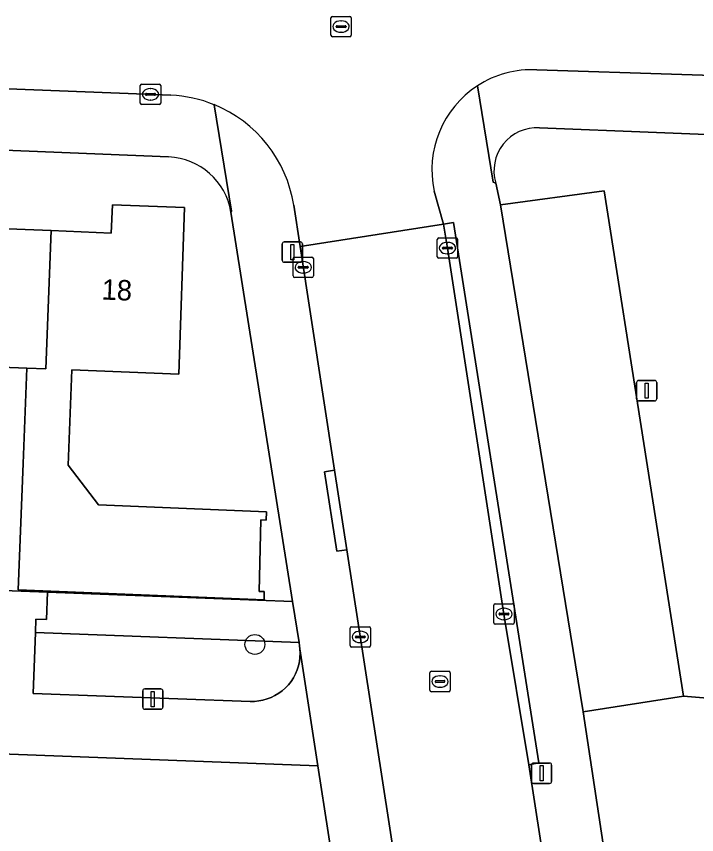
# Model space of a CAD drawing. Extents: x 160077 to 160948, y 386481 to 387498.
# Drawn here: x 160779.11 to 160812.49, y 386759.71 to 386799.88 of the extents above; entities that cross this region are included whole.
import ezdxf

# ---------------------------------------------------------------- set-up
doc = ezdxf.new("R2010")
doc.units = 0
for name, color, linetype in [('IMGEO_Boom', 7, 'Continuous'), ('IMGEO_Erf', 7, 'Continuous'), ('IMGEO_Groenvoorziening', 7, 'Continuous'), ('IMGEO_Kolk', 7, 'Continuous'), ('IMGEO_Lichtmast', 7, 'Continuous'), ('IMGEO_Pand', 7, 'Continuous'), ('IMGEO_Pand_nummerreeks', 7, 'Continuous'), ('IMGEO_Parkeervlak_open', 7, 'Continuous'), ('IMGEO_Rijbaan_lokaal_open', 7, 'Continuous'), ('IMGEO_Rioolput', 7, 'Continuous'), ('IMGEO_Voetpad_open', 7, 'Continuous')]:
    doc.layers.add(name, color=color, linetype=linetype)

msp = doc.modelspace()

# ---------------------------------------------------------------- linework, layer by layer
at = {"layer": 'IMGEO_Boom'}
msp.add_circle((160790.816, 386769.045), 0.489, dxfattribs=at)
at = {"layer": 'IMGEO_Erf'}
for points in [[(160786.582, 386792.975), (160742.734, 386794.767)], [(160728.911, 386794.383), (160726.113, 386793.887), (160729.208, 386773.55), (160739.777, 386773.151), (160742.325, 386773.055), (160752.485, 386772.671), (160755.107, 386772.572), (160765.268, 386772.187), (160767.757, 386772.092), (160778.031, 386771.702), (160780.646, 386771.604), (160792.664, 386771.147), (160789.642, 386790.266)], [(160774.463, 386789.613), (160780.828, 386789.358), (160783.769, 386789.24), (160783.823, 386790.625), (160787.36, 386790.487), (160787.081, 386782.314), (160781.843, 386782.518), (160781.659, 386777.84), (160783.144, 386775.898), (160791.386, 386775.56), (160791.376, 386775.148), (160791.104, 386775.155), (160791.018, 386771.649), (160791.271, 386771.643), (160791.265, 386771.227), (160779.206, 386771.72), (160779.444, 386777.926), (160779.627, 386782.604), (160775.467, 386782.766)]]:
    msp.add_lwpolyline(points, dxfattribs=at)
msp.add_lwpolyline([(160795.925, 386750), (160793.898, 386763.085), (160730.396, 386765.489), (160732.727, 386750), (160733.656, 386743.829), (160744.313, 386743.428), (160746.852, 386743.334), (160757.001, 386742.953), (160759.549, 386742.857), (160769.844, 386742.471), (160772.371, 386742.376), (160782.604, 386741.967), (160785.258, 386741.861), (160797.26, 386741.38)], close=True, dxfattribs=at)
msp.add_arc((160786.46, 386789.755), 3.222, 9.1259, 87.8375, dxfattribs=at)
at = {"layer": 'IMGEO_Groenvoorziening'}
for points in [[(160816.262, 386793.948), (160804.774, 386794.408)], [(160802.632, 386791.694), (160802.867, 386790.622), (160807.956, 386791.312), (160811.851, 386766.514), (160815.188, 386766.228), (160816.262, 386793.948)]]:
    msp.add_lwpolyline(points, dxfattribs=at)
for points in [[(160792.982, 386769.133), (160792.664, 386771.147), (160780.646, 386771.604), (160780.595, 386770.268), (160780.076, 386770.288), (160780.051, 386769.625)], [(160790.579, 386766.248), (160790.791, 386766.25), (160791.002, 386766.271), (160791.21, 386766.31), (160791.414, 386766.368), (160791.612, 386766.444), (160791.802, 386766.537), (160791.983, 386766.647), (160792.154, 386766.773), (160792.312, 386766.913), (160792.458, 386767.067), (160792.589, 386767.233), (160792.705, 386767.411), (160792.804, 386767.598), (160792.887, 386767.793), (160792.952, 386767.995), (160792.998, 386768.202), (160793.026, 386768.412), (160793.034, 386768.623), (160793.024, 386768.835), (160793.006, 386768.982), (160792.982, 386769.133), (160780.051, 386769.625), (160779.937, 386766.637)], [(160823.518, 386765.871), (160820.354, 386766.006), (160815.188, 386766.228), (160811.851, 386766.514), (160806.916, 386765.741), (160808.027, 386758.373), (160823.217, 386757.574)]]:
    msp.add_lwpolyline(points, close=True, dxfattribs=at)
msp.add_arc((160804.661, 386792.295), 2.116, 86.9395, 196.4966, dxfattribs=at)
at = {"layer": 'IMGEO_Kolk'}
for p, q in [((160785.195, 386795.623), (160785.195, 386796.475)), ((160785.27, 386796.549), (160786.122, 386796.549)), ((160785.683, 386796.329), (160785.708, 386796.329)), ((160786.196, 386796.475), (160786.196, 386795.623)), ((160785.454, 386796.043), (160785.454, 386796.055)), ((160785.892, 386796.006), (160785.494, 386796.006)), ((160785.497, 386796.092), (160785.895, 386796.092)), ((160785.938, 386796.055), (160785.938, 386796.043)), ((160786.122, 386795.549), (160785.27, 386795.549)), ((160785.706, 386795.769), (160785.681, 386795.769)), ((160799.764, 386788.075), (160799.764, 386788.927)), ((160799.839, 386789.001), (160800.691, 386789.001)), ((160800.252, 386788.781), (160800.277, 386788.781)), ((160800.765, 386788.927), (160800.765, 386788.075)), ((160800.023, 386788.495), (160800.023, 386788.507)), ((160800.461, 386788.458), (160800.063, 386788.458)), ((160800.066, 386788.544), (160800.464, 386788.544)), ((160800.507, 386788.507), (160800.507, 386788.495)), ((160792.688, 386787.132), (160792.688, 386787.984)), ((160792.763, 386788.058), (160793.615, 386788.058)), ((160793.689, 386787.984), (160793.689, 386787.132)), ((160800.691, 386788.001), (160799.839, 386788.001)), ((160800.275, 386788.221), (160800.25, 386788.221)), ((160792.947, 386787.552), (160792.947, 386787.564)), ((160793.385, 386787.515), (160792.987, 386787.515)), ((160792.99, 386787.601), (160793.388, 386787.601)), ((160793.176, 386787.838), (160793.201, 386787.838)), ((160793.431, 386787.564), (160793.431, 386787.552)), ((160793.199, 386787.278), (160793.174, 386787.278)), ((160793.615, 386787.058), (160792.763, 386787.058)), ((160802.611, 386771.039), (160803.463, 386771.039)), ((160802.536, 386770.113), (160802.536, 386770.965)), ((160803.024, 386770.819), (160803.049, 386770.819)), ((160803.537, 386770.965), (160803.537, 386770.113)), ((160802.795, 386770.533), (160802.795, 386770.545)), ((160803.233, 386770.496), (160802.835, 386770.496)), ((160802.838, 386770.582), (160803.236, 386770.582)), ((160803.047, 386770.259), (160803.022, 386770.259)), ((160803.279, 386770.545), (160803.279, 386770.533)), ((160795.489, 386768.988), (160795.489, 386769.84)), ((160795.564, 386769.914), (160796.416, 386769.914)), ((160796.49, 386769.84), (160796.49, 386768.988)), ((160803.463, 386770.039), (160802.611, 386770.039)), ((160795.748, 386769.408), (160795.748, 386769.42)), ((160795.791, 386769.457), (160796.189, 386769.457)), ((160795.977, 386769.694), (160796.002, 386769.694)), ((160796.232, 386769.42), (160796.232, 386769.408)), ((160796.186, 386769.371), (160795.788, 386769.371)), ((160796, 386769.134), (160795.975, 386769.134)), ((160796.416, 386768.914), (160795.564, 386768.914))]:
    msp.add_line(p, q, dxfattribs=at)
for points in [[(160785.195, 386795.623), (160785.195, 386796.475)], [(160785.27, 386796.549), (160786.122, 386796.549)], [(160786.196, 386796.475), (160786.196, 386795.623)], [(160786.122, 386795.549), (160785.27, 386795.549)], [(160799.764, 386788.075), (160799.764, 386788.927)], [(160799.839, 386789.001), (160800.691, 386789.001)], [(160800.765, 386788.927), (160800.765, 386788.075)], [(160792.688, 386787.132), (160792.688, 386787.984)], [(160792.763, 386788.058), (160793.615, 386788.058)], [(160793.689, 386787.984), (160793.689, 386787.132)], [(160800.691, 386788.001), (160799.839, 386788.001)], [(160793.615, 386787.058), (160792.763, 386787.058)], [(160802.611, 386771.039), (160803.463, 386771.039)], [(160802.536, 386770.113), (160802.536, 386770.965)], [(160803.537, 386770.965), (160803.537, 386770.113)], [(160795.489, 386768.988), (160795.489, 386769.84)], [(160795.564, 386769.914), (160796.416, 386769.914)], [(160796.49, 386769.84), (160796.49, 386768.988)], [(160803.463, 386770.039), (160802.611, 386770.039)], [(160796.416, 386768.914), (160795.564, 386768.914)]]:
    msp.add_lwpolyline(points, dxfattribs=at)
for centre, radius, start, end in [((160785.272, 386796.473), 0.0765, 91.552, 178.448), ((160785.272, 386796.473), 0.0765, 91.552, 178.448), ((160786.12, 386796.473), 0.0765, 1.552, 88.448), ((160786.12, 386796.473), 0.0765, 1.552, 88.448), ((160785.494, 386796.052), 0.0403, 85.8775, 175.7526), ((160785.491, 386796.042), 0.0366, 178.938, 274.7102), ((160785.895, 386796.049), 0.043, 264.8664, 352.4533), ((160785.899, 386796.054), 0.0386, 1.7309, 96.639), ((160785.272, 386795.625), 0.0765, 181.552, 268.448), ((160785.272, 386795.625), 0.0765, 181.552, 268.448), ((160786.12, 386795.625), 0.0765, 271.552, 358.448), ((160786.12, 386795.625), 0.0765, 271.552, 358.448), ((160799.841, 386788.925), 0.0765, 91.552, 178.448), ((160799.841, 386788.925), 0.0765, 91.552, 178.448), ((160800.689, 386788.925), 0.0765, 1.552, 88.448), ((160800.689, 386788.925), 0.0765, 1.552, 88.448), ((160800.063, 386788.504), 0.0403, 85.8775, 175.7526), ((160800.06, 386788.494), 0.0366, 178.938, 274.7102), ((160800.464, 386788.501), 0.043, 264.8664, 352.4533), ((160800.468, 386788.506), 0.0386, 1.7309, 96.639), ((160792.765, 386787.982), 0.0765, 91.552, 178.448), ((160792.765, 386787.982), 0.0765, 91.552, 178.448), ((160793.613, 386787.982), 0.0765, 1.552, 88.448), ((160793.613, 386787.982), 0.0765, 1.552, 88.448), ((160799.841, 386788.077), 0.0765, 181.552, 268.448), ((160799.841, 386788.077), 0.0765, 181.552, 268.448), ((160800.689, 386788.077), 0.0765, 271.552, 358.448), ((160800.689, 386788.077), 0.0765, 271.552, 358.448), ((160792.987, 386787.561), 0.0403, 85.8775, 175.7526), ((160792.984, 386787.551), 0.0366, 178.938, 274.7102), ((160793.388, 386787.558), 0.043, 264.8664, 352.4533), ((160793.392, 386787.563), 0.0386, 1.7309, 96.639), ((160792.765, 386787.134), 0.0765, 181.552, 268.448), ((160792.765, 386787.134), 0.0765, 181.552, 268.448), ((160793.613, 386787.134), 0.0765, 271.552, 358.448), ((160793.613, 386787.134), 0.0765, 271.552, 358.448), ((160802.613, 386770.963), 0.0765, 91.552, 178.448), ((160802.613, 386770.963), 0.0765, 91.552, 178.448), ((160803.461, 386770.963), 0.0765, 1.552, 88.448), ((160803.461, 386770.963), 0.0765, 1.552, 88.448), ((160802.835, 386770.542), 0.0403, 85.8775, 175.7526), ((160802.832, 386770.532), 0.0366, 178.938, 274.7102), ((160803.236, 386770.539), 0.043, 264.8664, 352.4533), ((160803.24, 386770.544), 0.0386, 1.7309, 96.639), ((160795.566, 386769.838), 0.0765, 91.552, 178.448), ((160795.566, 386769.838), 0.0765, 91.552, 178.448), ((160796.414, 386769.838), 0.0765, 1.552, 88.448), ((160796.414, 386769.838), 0.0765, 1.552, 88.448), ((160802.613, 386770.115), 0.0765, 181.552, 268.448), ((160802.613, 386770.115), 0.0765, 181.552, 268.448), ((160803.461, 386770.115), 0.0765, 271.552, 358.448), ((160803.461, 386770.115), 0.0765, 271.552, 358.448), ((160795.788, 386769.417), 0.0403, 85.8775, 175.7526), ((160795.785, 386769.407), 0.0366, 178.938, 274.7102), ((160796.189, 386769.414), 0.043, 264.8664, 352.4533), ((160796.193, 386769.419), 0.0386, 1.7309, 96.639), ((160795.566, 386768.99), 0.0765, 181.552, 268.448), ((160795.566, 386768.99), 0.0765, 181.552, 268.448), ((160796.414, 386768.99), 0.0765, 271.552, 358.448), ((160796.414, 386768.99), 0.0765, 271.552, 358.448)]:
    msp.add_arc(centre, radius, start, end, dxfattribs=at)
for centre, major_axis, ratio, start_param, end_param in [((160785.682, 386796.049), (-0.387, 0.002), 0.722429, 4.712389, 7.853982), ((160785.707, 386796.049), (-0.39, 0.002), 0.717154, 1.570796, 4.712389), ((160800.251, 386788.501), (-0.387, 0.002), 0.722429, 4.712389, 7.853982), ((160800.276, 386788.501), (-0.39, 0.002), 0.717154, 1.570796, 4.712389), ((160793.175, 386787.558), (-0.387, 0.002), 0.722429, 4.712389, 7.853982), ((160793.2, 386787.558), (-0.39, 0.002), 0.717154, 1.570796, 4.712389), ((160803.023, 386770.539), (-0.387, 0.002), 0.722429, 4.712389, 7.853982), ((160803.048, 386770.539), (-0.39, 0.002), 0.717154, 1.570796, 4.712389), ((160795.976, 386769.414), (-0.387, 0.002), 0.722429, 4.712389, 7.853982), ((160796.001, 386769.414), (-0.39, 0.002), 0.717154, 1.570796, 4.712389)]:
    msp.add_ellipse(centre, major_axis=major_axis, ratio=ratio, start_param=start_param, end_param=end_param, dxfattribs=at)
at = {"layer": 'IMGEO_Lichtmast'}
for p, q in [((160792.159, 386787.904), (160792.159, 386788.704)), ((160792.159, 386788.704), (160792.159, 386787.904)), ((160792.259, 386788.804), (160793.049, 386788.804)), ((160793.049, 386788.804), (160792.259, 386788.804)), ((160793.149, 386788.704), (160793.149, 386787.904)), ((160793.149, 386787.904), (160793.149, 386788.704)), ((160793.049, 386787.804), (160792.259, 386787.804)), ((160792.259, 386787.804), (160793.049, 386787.804)), ((160809.54, 386781.103), (160809.54, 386781.903)), ((160809.54, 386781.903), (160809.54, 386781.103)), ((160809.64, 386782.003), (160810.43, 386782.003)), ((160810.43, 386782.003), (160809.64, 386782.003)), ((160810.53, 386781.903), (160810.53, 386781.103)), ((160810.53, 386781.103), (160810.53, 386781.903)), ((160810.43, 386781.003), (160809.64, 386781.003)), ((160809.64, 386781.003), (160810.43, 386781.003)), ((160785.312, 386765.964), (160785.312, 386766.764)), ((160785.312, 386766.764), (160785.312, 386765.964)), ((160785.412, 386766.864), (160786.202, 386766.864)), ((160786.202, 386766.864), (160785.412, 386766.864)), ((160786.302, 386766.764), (160786.302, 386765.964)), ((160786.302, 386765.964), (160786.302, 386766.764)), ((160786.202, 386765.864), (160785.412, 386765.864)), ((160785.412, 386765.864), (160786.202, 386765.864)), ((160804.386, 386762.324), (160804.386, 386763.124)), ((160804.386, 386763.124), (160804.386, 386762.324)), ((160804.486, 386763.224), (160805.276, 386763.224)), ((160805.276, 386763.224), (160804.486, 386763.224)), ((160805.376, 386763.124), (160805.376, 386762.324)), ((160805.376, 386762.324), (160805.376, 386763.124)), ((160805.276, 386762.224), (160804.486, 386762.224)), ((160804.486, 386762.224), (160805.276, 386762.224))]:
    msp.add_line(p, q, dxfattribs=at)
for points in [[(160792.579, 386788.679), (160792.729, 386788.679), (160792.729, 386787.929), (160792.579, 386787.929), (160792.579, 386788.679)], [(160809.96, 386781.878), (160810.11, 386781.878), (160810.11, 386781.128), (160809.96, 386781.128), (160809.96, 386781.878)], [(160785.732, 386766.739), (160785.882, 386766.739), (160785.882, 386765.989), (160785.732, 386765.989), (160785.732, 386766.739)], [(160804.806, 386763.099), (160804.956, 386763.099), (160804.956, 386762.349), (160804.806, 386762.349), (160804.806, 386763.099)]]:
    msp.add_lwpolyline(points, dxfattribs=at)
for centre, start, end in [((160792.259, 386788.704), 90, 180), ((160792.259, 386788.704), 90, 180), ((160793.049, 386788.704), 0, 90), ((160793.049, 386788.704), 360, 90), ((160792.259, 386787.904), 180, 270), ((160792.259, 386787.904), 180, 270), ((160793.049, 386787.904), 270, 0), ((160793.049, 386787.904), 270, 0), ((160809.64, 386781.903), 90, 180), ((160809.64, 386781.903), 90, 180), ((160810.43, 386781.903), 0, 90), ((160810.43, 386781.903), 360, 90), ((160809.64, 386781.103), 180, 270), ((160809.64, 386781.103), 180, 270), ((160810.43, 386781.103), 270, 0), ((160810.43, 386781.103), 270, 0), ((160785.412, 386766.764), 90, 180), ((160785.412, 386766.764), 90, 180), ((160786.202, 386766.764), 0, 90), ((160786.202, 386766.764), 360, 90), ((160785.412, 386765.964), 180, 270), ((160785.412, 386765.964), 180, 270), ((160786.202, 386765.964), 270, 0), ((160786.202, 386765.964), 270, 0), ((160804.486, 386763.124), 90, 180), ((160804.486, 386763.124), 90, 180), ((160805.276, 386763.124), 0, 90), ((160805.276, 386763.124), 360, 90), ((160804.486, 386762.324), 180, 270), ((160804.486, 386762.324), 180, 270), ((160805.276, 386762.324), 270, 0), ((160805.276, 386762.324), 270, 0)]:
    msp.add_arc(centre, 0.1, start, end, dxfattribs=at)
at = {"layer": 'IMGEO_Pand'}
for points in [[(160787.36, 386790.487), (160783.823, 386790.625), (160783.769, 386789.24), (160780.828, 386789.358), (160780.556, 386782.568), (160779.627, 386782.604), (160779.444, 386777.926), (160779.206, 386771.72), (160791.265, 386771.227), (160791.271, 386771.643), (160791.018, 386771.649), (160791.104, 386775.155), (160791.376, 386775.148), (160791.386, 386775.56), (160783.144, 386775.898), (160781.659, 386777.84), (160781.843, 386782.518), (160787.081, 386782.314)], [(160780.828, 386789.358), (160774.463, 386789.613), (160774.191, 386782.815), (160773.251, 386782.852), (160773.138, 386779.948), (160773.069, 386778.174), (160774.003, 386778.137), (160775.284, 386778.087), (160775.467, 386782.766), (160779.627, 386782.604), (160780.556, 386782.568)]]:
    msp.add_lwpolyline(points, close=True, dxfattribs=at)
at = {"layer": 'IMGEO_Parkeervlak_open'}
msp.add_lwpolyline([(160806.916, 386765.741), (160811.851, 386766.514), (160807.956, 386791.312), (160802.867, 386790.622)], close=True, dxfattribs=at)
at = {"layer": 'IMGEO_Rijbaan_lokaal_open'}
for points in [[(160837.242, 386800.967), (160811.348, 386802.129), (160793.676, 386802.846), (160774.115, 386803.537), (160744.509, 386804.715), (160744.23, 386797.66), (160786.696, 386796.006)], [(160804.647, 386797.253), (160818.878, 386796.791), (160820.826, 386796.796), (160828.943, 386796.404), (160836.761, 386796.159), (160837.049, 386796.144), (160837.242, 386800.967)], [(160792.719, 386790.606), (160793.031, 386788.583), (160800.062, 386789.668), (160799.617, 386791.295)], [(160813.836, 386700.495), (160810.411, 386722.747), (160809.998, 386725.345), (160806.912, 386744.746), (160806.241, 386750), (160805.996, 386751.914), (160804.256, 386763.136), (160803.036, 386770.539), (160800.264, 386788.501), (160800.062, 386789.668), (160793.031, 386788.583), (160794.727, 386777.599), (160795.33, 386773.695), (160798.275, 386754.619), (160798.992, 386750), (160802.535, 386727.194), (160807.755, 386694.276), (160809.921, 386680.44), (160810.008, 386680.46), (160812.135, 386661.504), (160812.011, 386661.39), (160810.958, 386636.637), (160810.118, 386615.402)]]:
    msp.add_lwpolyline(points, dxfattribs=at)
for centre, radius, start, end in [((160804.404, 386792.363), 4.896, 87.1517, 122.9613), ((160804.404, 386792.355), 4.903, 122.9151, 192.4817), ((160786.416, 386789.637), 6.375, 67.858, 87.4848), ((160786.414, 386789.633), 6.38, 8.7732, 67.8522)]:
    msp.add_arc(centre, radius, start, end, dxfattribs=at)
at = {"layer": 'IMGEO_Rioolput'}
for p, q in [((160794.545, 386798.95), (160794.545, 386799.802)), ((160794.62, 386799.876), (160795.472, 386799.876)), ((160795.033, 386799.656), (160795.058, 386799.656)), ((160795.546, 386799.802), (160795.546, 386798.95)), ((160794.804, 386799.37), (160794.804, 386799.382)), ((160795.242, 386799.333), (160794.844, 386799.333)), ((160794.847, 386799.419), (160795.245, 386799.419)), ((160795.288, 386799.382), (160795.288, 386799.37)), ((160795.472, 386798.876), (160794.62, 386798.876)), ((160795.056, 386799.096), (160795.031, 386799.096)), ((160799.4, 386766.799), (160799.4, 386767.651)), ((160799.475, 386767.725), (160800.327, 386767.725)), ((160799.888, 386767.505), (160799.913, 386767.505)), ((160800.401, 386767.651), (160800.401, 386766.799)), ((160799.659, 386767.219), (160799.659, 386767.231)), ((160800.097, 386767.182), (160799.699, 386767.182)), ((160799.702, 386767.268), (160800.1, 386767.268)), ((160800.143, 386767.231), (160800.143, 386767.219)), ((160800.327, 386766.725), (160799.475, 386766.725)), ((160799.911, 386766.945), (160799.886, 386766.945))]:
    msp.add_line(p, q, dxfattribs=at)
for points in [[(160794.545, 386798.95), (160794.545, 386799.802)], [(160794.62, 386799.876), (160795.472, 386799.876)], [(160795.546, 386799.802), (160795.546, 386798.95)], [(160795.472, 386798.876), (160794.62, 386798.876)], [(160799.4, 386766.799), (160799.4, 386767.651)], [(160799.475, 386767.725), (160800.327, 386767.725)], [(160800.401, 386767.651), (160800.401, 386766.799)], [(160800.327, 386766.725), (160799.475, 386766.725)]]:
    msp.add_lwpolyline(points, dxfattribs=at)
for centre, radius, start, end in [((160794.622, 386799.8), 0.0765, 91.552, 178.448), ((160794.622, 386799.8), 0.0765, 91.552, 178.448), ((160795.47, 386799.8), 0.0765, 1.552, 88.448), ((160795.47, 386799.8), 0.0765, 1.552, 88.448), ((160794.844, 386799.379), 0.0403, 85.8775, 175.7526), ((160794.841, 386799.369), 0.0366, 178.938, 274.7102), ((160795.245, 386799.376), 0.043, 264.8664, 352.4533), ((160795.249, 386799.381), 0.0386, 1.7309, 96.639), ((160794.622, 386798.952), 0.0765, 181.552, 268.448), ((160794.622, 386798.952), 0.0765, 181.552, 268.448), ((160795.47, 386798.952), 0.0765, 271.552, 358.448), ((160795.47, 386798.952), 0.0765, 271.552, 358.448), ((160799.477, 386767.649), 0.0765, 91.552, 178.448), ((160799.477, 386767.649), 0.0765, 91.552, 178.448), ((160800.325, 386767.649), 0.0765, 1.552, 88.448), ((160800.325, 386767.649), 0.0765, 1.552, 88.448), ((160799.699, 386767.228), 0.0403, 85.8775, 175.7526), ((160799.696, 386767.218), 0.0366, 178.938, 274.7102), ((160800.1, 386767.225), 0.043, 264.8664, 352.4533), ((160800.104, 386767.23), 0.0386, 1.7309, 96.639), ((160799.477, 386766.801), 0.0765, 181.552, 268.448), ((160799.477, 386766.801), 0.0765, 181.552, 268.448), ((160800.325, 386766.801), 0.0765, 271.552, 358.448), ((160800.325, 386766.801), 0.0765, 271.552, 358.448)]:
    msp.add_arc(centre, radius, start, end, dxfattribs=at)
for centre, major_axis, ratio, start_param, end_param in [((160795.032, 386799.376), (-0.387, 0.002), 0.722429, 4.712389, 7.853982), ((160795.057, 386799.376), (-0.39, 0.002), 0.717154, 1.570796, 4.712389), ((160799.887, 386767.225), (-0.387, 0.002), 0.722429, 4.712389, 7.853982), ((160799.912, 386767.225), (-0.39, 0.002), 0.717154, 1.570796, 4.712389)]:
    msp.add_ellipse(centre, major_axis=major_axis, ratio=ratio, start_param=start_param, end_param=end_param, dxfattribs=at)
at = {"layer": 'IMGEO_Voetpad_open'}
for points in [[(160786.696, 386796.006), (160744.23, 386797.66)], [(160837.448, 386796.123), (160837.049, 386796.144), (160836.761, 386796.159), (160828.943, 386796.404), (160828.919, 386795.905), (160820.802, 386796.297), (160820.826, 386796.796), (160818.878, 386796.791), (160804.647, 386797.253)], [(160812.902, 386726.822), (160810.536, 386741.865), (160811.572, 386741.979), (160811.075, 386744.88), (160810.081, 386744.76), (160809.736, 386746.952), (160809.27, 386750), (160808.027, 386758.373), (160806.916, 386765.741), (160802.867, 386790.622), (160802.632, 386791.694), (160802.511, 386791.738), (160801.74, 386796.471)], [(160801.74, 386796.471), (160802.511, 386791.738), (160802.632, 386791.694)], [(160788.819, 386795.542), (160789.675, 386790.315), (160789.642, 386790.266), (160792.664, 386771.147), (160792.982, 386769.133), (160793.006, 386768.982), (160793.024, 386768.835), (160793.898, 386763.085), (160795.925, 386750)], [(160789.642, 386790.266), (160789.675, 386790.315), (160788.819, 386795.542)], [(160742.734, 386794.767), (160786.582, 386792.975)], [(160804.774, 386794.408), (160816.262, 386793.948), (160821.444, 386793.739), (160827.385, 386793.504), (160832.353, 386793.38), (160832.32, 386792.519), (160836.219, 386792.375), (160835.977, 386786.254)], [(160799.617, 386791.295), (160800.062, 386789.668), (160800.555, 386789.754), (160804.746, 386763.241), (160804.256, 386763.136), (160805.996, 386751.914), (160806.241, 386750), (160806.912, 386744.746), (160809.998, 386725.345), (160811.089, 386725.486), (160816.298, 386692.41)], [(160802.535, 386727.194), (160798.992, 386750), (160798.275, 386754.619), (160795.33, 386773.695), (160794.836, 386773.62), (160794.233, 386777.524), (160794.727, 386777.599), (160793.031, 386788.583), (160792.719, 386790.606)], [(160730.396, 386765.489), (160793.898, 386763.085), (160793.024, 386768.835), (160793.034, 386768.623), (160793.026, 386768.412), (160792.998, 386768.202), (160792.952, 386767.995), (160792.887, 386767.793), (160792.804, 386767.598), (160792.705, 386767.411), (160792.589, 386767.233), (160792.458, 386767.067), (160792.312, 386766.913), (160792.154, 386766.773), (160791.983, 386766.647), (160791.802, 386766.537), (160791.612, 386766.444), (160791.414, 386766.368), (160791.21, 386766.31), (160791.002, 386766.271), (160790.791, 386766.25), (160790.579, 386766.248), (160779.937, 386766.637), (160780.051, 386769.625), (160780.076, 386770.288), (160780.595, 386770.268), (160780.646, 386771.604), (160778.031, 386771.702)]]:
    msp.add_lwpolyline(points, dxfattribs=at)
for points in [[(160804.256, 386763.136), (160804.746, 386763.241), (160800.555, 386789.754), (160800.062, 386789.668), (160800.264, 386788.501), (160803.036, 386770.539)], [(160794.727, 386777.599), (160794.233, 386777.524), (160794.836, 386773.62), (160795.33, 386773.695)]]:
    msp.add_lwpolyline(points, close=True, dxfattribs=at)
for centre, radius, start, end in [((160804.404, 386792.363), 4.896, 87.1517, 122.9613), ((160804.404, 386792.355), 4.903, 122.9151, 192.4817), ((160786.416, 386789.637), 6.375, 67.858, 87.4848), ((160786.414, 386789.633), 6.38, 8.7732, 67.8522), ((160804.661, 386792.295), 2.116, 86.9395, 196.4966), ((160786.46, 386789.755), 3.222, 9.1259, 87.8375)]:
    msp.add_arc(centre, radius, start, end, dxfattribs=at)

# ---------------------------------------------------------------- texts
at = {"layer": 'IMGEO_Pand_nummerreeks'}
msp.add_text('18', height=1, rotation=357.7024, dxfattribs=at).set_placement((160783.283, 386785.978))

doc.saveas('drawing.dxf')
